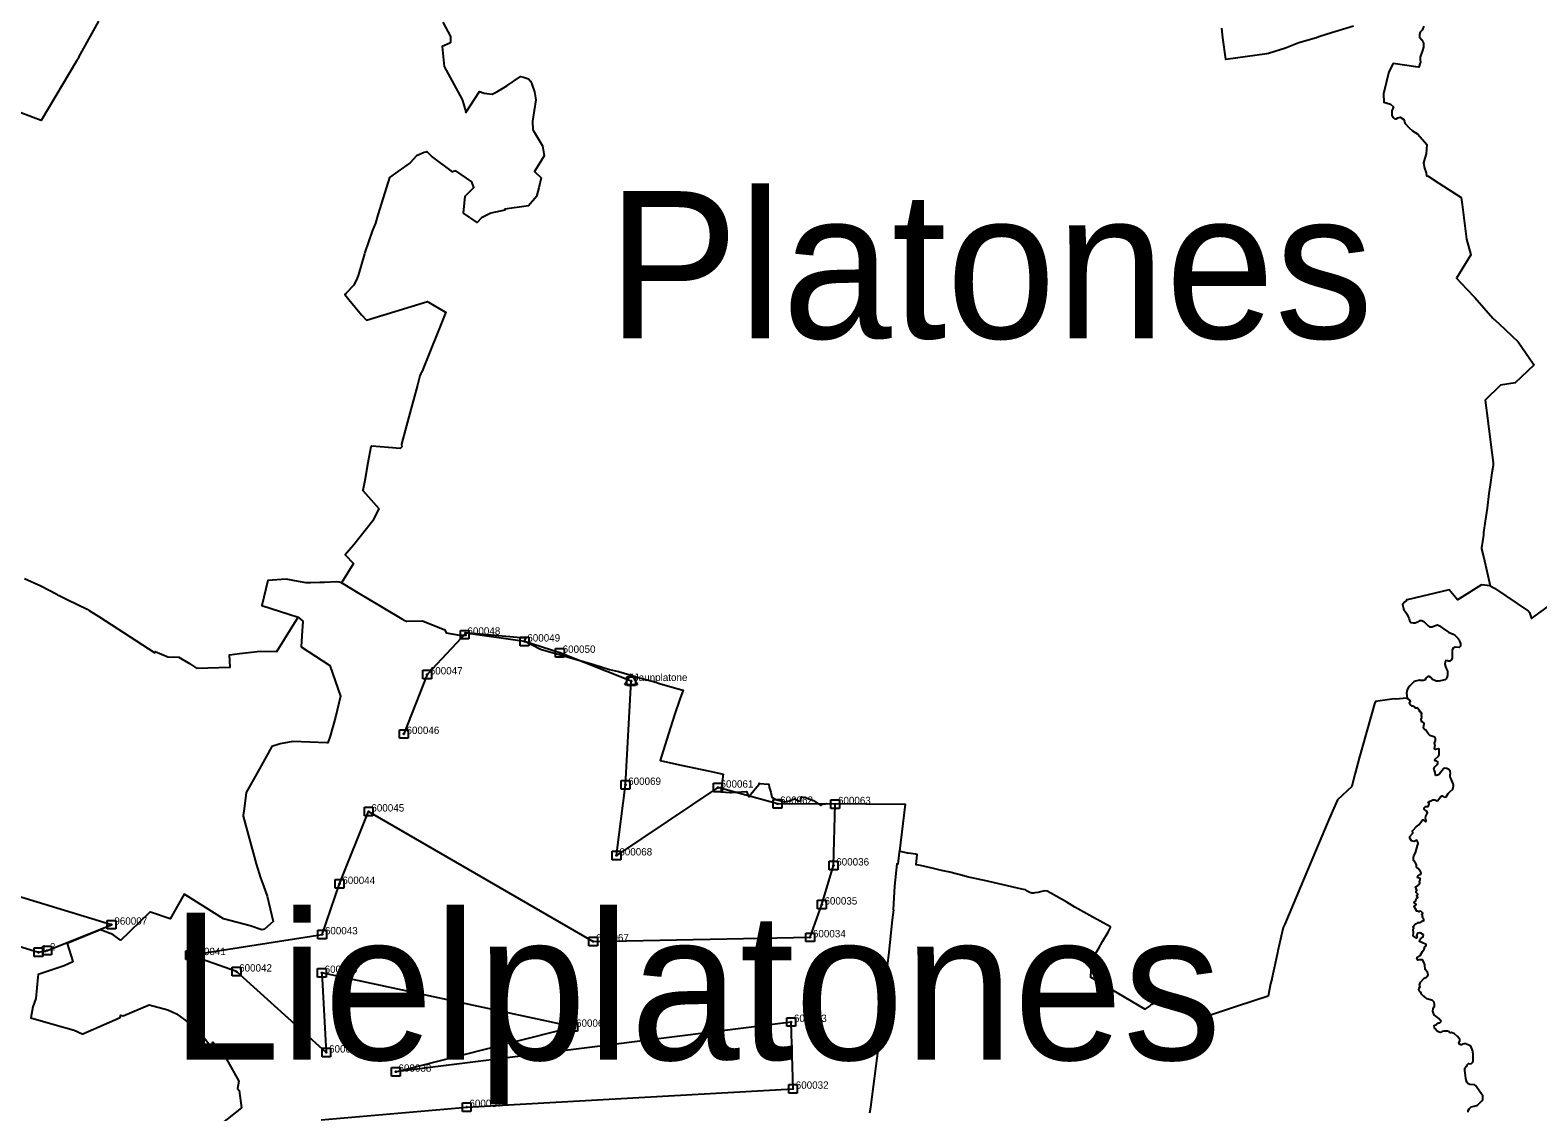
# Model space of a CAD drawing. Extents: x 462479 to 502016, y 241775 to 305873.
# Drawn here: x 474079 to 486368, y 257820 to 266634 of the extents above; entities that cross this region are included whole.
import ezdxf

# ---------------------------------------------------------------- set-up
doc = ezdxf.new("R2010")
doc.units = 0
for name, color, linetype in [('Default', 7, 'Continuous'), ('Level 19', 7, 'Continuous'), ('Level 51', 7, 'Continuous'), ('pagastu_nosaukumi', 7, 'Continuous'), ('pagastu_robezas', 7, 'Continuous')]:
    doc.layers.add(name, color=color, linetype=linetype)

msp = doc.modelspace()

# ---------------------------------------------------------------- linework, layer by layer
at = {"layer": 'Default'}
for points in [[(476451, 257755), (477637, 257859), (480297, 258008), (480282, 258552), (477059, 258147), (478506, 258513), (476457, 258952), (476493, 258303), (475760, 258963), (475384, 259097), (476459, 259266), (476601, 259677), (476838, 260267), (478669, 259209), (480437, 259242), (480531, 259509), (480627, 259827), (480641, 260327), (480170, 260330), (479684, 260462), (478859, 259909), (478931, 260484), (478977, 261330), (478397, 261560), (478109, 261652), (477631, 261720), (477314, 261384), (477124, 260899)], [(473787, 259230), (474148, 259120), (474218, 259135), (474743, 259345), (473431, 259743)]]:
    msp.add_lwpolyline(points, dxfattribs=at)
at = {"layer": 'Level 19'}
for p, q in [((477586, 261743), (477656, 261743)), ((477586, 261673), (477586, 261743)), ((477656, 261673), (477586, 261673)), ((477656, 261743), (477656, 261673)), ((478074, 261687), (478144, 261687)), ((478074, 261617), (478074, 261687)), ((478144, 261687), (478144, 261617)), ((478144, 261617), (478074, 261617)), ((478362, 261595), (478432, 261595)), ((478362, 261525), (478362, 261595)), ((478432, 261525), (478362, 261525)), ((478432, 261595), (478432, 261525)), ((477279, 261419), (477349, 261419)), ((477279, 261349), (477279, 261419)), ((477349, 261419), (477349, 261349)), ((477349, 261349), (477279, 261349)), ((478925, 261299), (478977, 261390)), ((479030, 261299), (478925, 261299)), ((478942, 261365), (479012, 261365)), ((478942, 261295), (478942, 261365)), ((478942, 261365), (479012, 261365)), ((478942, 261295), (478942, 261365)), ((478942, 261365), (479012, 261365)), ((478942, 261295), (478942, 261365)), ((479012, 261295), (478942, 261295)), ((479012, 261295), (478942, 261295)), ((479012, 261295), (478942, 261295)), ((478977, 261390), (479030, 261299)), ((479012, 261365), (479012, 261295)), ((479012, 261365), (479012, 261295)), ((479012, 261365), (479012, 261295)), ((477089, 260934), (477159, 260934)), ((477089, 260864), (477089, 260934)), ((477159, 260934), (477159, 260864)), ((477159, 260864), (477089, 260864)), ((478896, 260519), (478966, 260519)), ((478896, 260449), (478896, 260519)), ((478966, 260449), (478896, 260449)), ((478966, 260519), (478966, 260449)), ((479649, 260497), (479719, 260497)), ((479649, 260427), (479649, 260497)), ((479719, 260427), (479649, 260427)), ((479719, 260497), (479719, 260427)), ((476803, 260302), (476873, 260302)), ((476803, 260232), (476803, 260302)), ((476873, 260302), (476873, 260232)), ((480135, 260365), (480205, 260365)), ((480135, 260295), (480135, 260365)), ((480205, 260295), (480135, 260295)), ((480205, 260365), (480205, 260295)), ((480606, 260362), (480676, 260362)), ((480606, 260292), (480606, 260362)), ((480676, 260292), (480606, 260292)), ((480676, 260362), (480676, 260292)), ((476873, 260232), (476803, 260232)), ((478824, 259944), (478894, 259944)), ((478824, 259874), (478824, 259944)), ((478894, 259944), (478894, 259874)), ((478894, 259874), (478824, 259874)), ((480592, 259862), (480662, 259862)), ((480592, 259792), (480592, 259862)), ((480662, 259862), (480662, 259792)), ((476566, 259712), (476636, 259712)), ((476566, 259642), (476566, 259712)), ((476636, 259712), (476636, 259642)), ((480662, 259792), (480592, 259792)), ((476636, 259642), (476566, 259642)), ((480496, 259544), (480566, 259544)), ((480496, 259474), (480496, 259544)), ((480566, 259474), (480496, 259474)), ((480566, 259544), (480566, 259474)), ((474708, 259380), (474778, 259380)), ((474708, 259310), (474708, 259380)), ((474778, 259310), (474708, 259310)), ((474778, 259380), (474778, 259310)), ((476424, 259301), (476494, 259301)), ((476424, 259231), (476424, 259301)), ((476494, 259231), (476424, 259231)), ((476494, 259301), (476494, 259231)), ((478634, 259244), (478704, 259244)), ((478634, 259174), (478634, 259244)), ((478704, 259244), (478704, 259174)), ((480402, 259277), (480472, 259277)), ((480402, 259207), (480402, 259277)), ((480472, 259207), (480402, 259207)), ((480472, 259277), (480472, 259207)), ((474113, 259155), (474183, 259155)), ((474113, 259085), (474113, 259155)), ((474183, 259085), (474113, 259085)), ((474183, 259170), (474253, 259170)), ((474183, 259100), (474183, 259170)), ((474183, 259155), (474183, 259085)), ((474253, 259100), (474183, 259100)), ((474253, 259170), (474253, 259100)), ((475349, 259132), (475419, 259132)), ((475349, 259062), (475349, 259132)), ((475419, 259062), (475349, 259062)), ((475419, 259132), (475419, 259062)), ((478704, 259174), (478634, 259174)), ((475725, 258998), (475795, 258998)), ((475725, 258928), (475725, 258998)), ((475795, 258998), (475795, 258928)), ((476422, 258987), (476492, 258987)), ((476422, 258917), (476422, 258987)), ((476492, 258987), (476492, 258917)), ((475795, 258928), (475725, 258928)), ((476492, 258917), (476422, 258917)), ((480247, 258587), (480317, 258587)), ((480247, 258517), (480247, 258587)), ((480317, 258587), (480317, 258517)), ((478471, 258548), (478541, 258548)), ((478471, 258478), (478471, 258548)), ((478541, 258478), (478471, 258478)), ((478541, 258548), (478541, 258478)), ((480317, 258517), (480247, 258517)), ((476458, 258338), (476528, 258338)), ((476458, 258268), (476458, 258338)), ((476458, 258338), (476528, 258338)), ((476458, 258268), (476458, 258338)), ((476528, 258338), (476528, 258268)), ((476528, 258338), (476528, 258268)), ((476528, 258268), (476458, 258268)), ((476528, 258268), (476458, 258268)), ((477024, 258182), (477094, 258182)), ((477024, 258112), (477024, 258182)), ((477094, 258112), (477024, 258112)), ((477094, 258182), (477094, 258112)), ((480262, 258043), (480332, 258043)), ((480262, 257973), (480262, 258043)), ((480332, 257973), (480262, 257973)), ((480332, 258043), (480332, 257973)), ((477602, 257894), (477672, 257894)), ((477602, 257824), (477602, 257894)), ((477672, 257894), (477672, 257824)), ((477672, 257824), (477602, 257824))]:
    msp.add_line(p, q, dxfattribs=at)
for centre in [(477621, 261708), (478109, 261652), (478397, 261560), (477314, 261384), (478977, 261330), (478977, 261330), (478977, 261330), (478977, 261330), (477124, 260899), (478931, 260484), (479684, 260462), (480170, 260330), (480641, 260327), (476838, 260267), (478859, 259909), (480627, 259827), (476601, 259677), (480531, 259509), (474743, 259345), (476459, 259265), (478669, 259209), (480437, 259242), (474148, 259119), (474218, 259135), (475384, 259097), (475760, 258962), (476457, 258952), (478506, 258513), (480282, 258552), (476493, 258303), (476493, 258303), (477059, 258147), (480297, 258008), (477637, 257859)]:
    msp.add_circle(centre, 3.5, dxfattribs=at)
at = {"layer": 'pagastu_robezas'}
for points in [[(474637, 266706), (474474, 266413), (474476, 266407), (474459, 266386), (474170, 265897), (474003, 265959)], [(477442, 266700), (477505, 266582), (477505, 266533), (477501, 266529), (477437, 266500), (477451, 266365), (477453, 266338), (477599, 266069), (477601, 266066), (477604, 266061), (477630, 265969), (477631, 265964), (477742, 266135), (477779, 266121), (477845, 266111), (477884, 266131), (477965, 266180), (478077, 266256), (478099, 266250), (478142, 266236), (478158, 266218), (478168, 266197), (478169, 266195), (478191, 266131), (478200, 266067), (478173, 265892), (478177, 265820), (478181, 265814), (478256, 265692), (478270, 265611), (478189, 265483), (478244, 265431), (478224, 265348), (478210, 265290), (478208, 265282), (478141, 265202), (477948, 265174), (477949, 265167), (477834, 265143), (477758, 265104), (477722, 265066), (477610, 265143), (477626, 265282), (477695, 265353), (477679, 265397), (477550, 265487), (477522, 265480), (477350, 265607), (477311, 265644), (477303, 265641), (477291, 265636), (477229, 265611), (477177, 265552), (477076, 265481), (477008, 265432), (476915, 265136), (476912, 265128), (476893, 265061), (476866, 264996), (476808, 264821), (476804, 264811), (476754, 264643), (476744, 264613), (476718, 264557), (476651, 264488), (476649, 264483), (476644, 264481), (476676, 264439), (476781, 264313), (476820, 264270), (477319, 264422), (477320, 264421), (477327, 264417), (477465, 264337), (477468, 264335), (477274, 263854), (477271, 263846), (477263, 263837), (477256, 263818), (477236, 263742), (477166, 263482), (477107, 263261), (477109, 263240), (477096, 263225), (476999, 263232), (477000, 263234), (476864, 263243), (476858, 263241), (476856, 263238), (476831, 263108), (476806, 262964), (476791, 262883), (476922, 262736), (476872, 262636), (476718, 262440), (476646, 262359), (476715, 262288), (476618, 262131)], [(483789, 266649), (483799, 266570), (483822, 266398), (483826, 266398), (484160, 266443), (484172, 266447), (484311, 266491), (484419, 266533), (484563, 266575), (484582, 266581), (484652, 266604), (484865, 266670)], [(485439, 266666), (485424, 266633), (485410, 266617), (485404, 266599), (485403, 266577), (485422, 266555), (485435, 266529), (485435, 266496), (485428, 266469), (485415, 266430), (485409, 266413), (485409, 266393), (485411, 266374), (485409, 266368), (485398, 266331), (485375, 266334), (485188, 266363), (485154, 266295), (485109, 266115), (485112, 266047), (485167, 266030), (485193, 266009), (485177, 265977), (485178, 265942), (485186, 265921), (485202, 265912), (485213, 265912), (485227, 265920), (485246, 265925), (485276, 265907), (485280, 265890), (485283, 265876), (485319, 265838), (485346, 265814), (485391, 265785), (485463, 265703), (485459, 265627), (485446, 265592), (485436, 265553), (485443, 265508), (485459, 265470), (485461, 265448), (485473, 265444), (485560, 265387), (485744, 265270), (485751, 265214), (485759, 265147), (485786, 264930), (485821, 264803), (485704, 264614), (485787, 264527), (485855, 264455), (486002, 264287), (486052, 264240), (486207, 264094), (486332, 263913), (486336, 263903), (486183, 263761), (486065, 263742), (485940, 263619), (485958, 263472), (485966, 263405), (485971, 263367), (485982, 263276), (486004, 263107), (486003, 263087), (485993, 263028), (485979, 262929), (485969, 262858), (485954, 262738), (485939, 262632), (485926, 262541), (485925, 262539), (485924, 262520), (485910, 262416), (485910, 262407), (485927, 262335), (485980, 262105)], [(474032, 262166), (474166, 262105), (474297, 262037), (474301, 262032), (474316, 262026), (474380, 261995), (474545, 261915), (474561, 261906), (474638, 261856), (475094, 261559), (475099, 261570), (475202, 261527), (475292, 261524), (475378, 261472), (475434, 261436), (475709, 261444), (475705, 261545), (475785, 261554), (475860, 261562), (475954, 261573), (476091, 261572), (476264, 261851)], [(476618, 262131), (476599, 262137), (476574, 262138), (476479, 262134), (476441, 262132), (476364, 262130), (476329, 262130), (476267, 262140), (476167, 262160), (476015, 262149), (475968, 261947), (476264, 261851)], [(476618, 262131), (476622, 262128), (476628, 262124), (476767, 262041), (476812, 262014), (477109, 261838), (477134, 261823), (477147, 261818), (477149, 261817), (477276, 261821), (477458, 261747), (477469, 261722), (477578, 261703), (477627, 261704), (477633, 261705), (477624, 261726), (478079, 261686), (478119, 261683), (478107, 261659), (478166, 261629), (478240, 261589), (478674, 261464), (478801, 261425), (478875, 261408), (478995, 261373), (479014, 261367), (479028, 261362), (479178, 261320), (479210, 261311), (479350, 261270), (479401, 261255), (479374, 261183), (479332, 261055), (479267, 260848), (479213, 260684), (479371, 260648), (479619, 260597), (479729, 260572), (479709, 260428), (479786, 260422), (479794, 260421), (479837, 260424), (479919, 260429), (479937, 260388), (479942, 260394), (479989, 260452), (480020, 260491), (480023, 260497), (480027, 260496), (480095, 260490), (480101, 260490), (480103, 260465), (480115, 260425), (480125, 260385), (480155, 260368), (480164, 260363), (480230, 260347), (480268, 260353), (480309, 260370), (480347, 260351), (480362, 260357), (480361, 260370), (480367, 260386), (480395, 260380), (480413, 260376), (480464, 260357), (480525, 260317), (480534, 260325), (480536, 260331), (480562, 260330), (480571, 260333), (481211, 260328), (481164, 259943)], [(485980, 262105), (485909, 262114), (485726, 262001), (485713, 261992), (485646, 262074), (485302, 261993), (485297, 261991), (485294, 261983), (485283, 261975), (485265, 261953), (485272, 261920), (485277, 261909), (485288, 261897), (485301, 261879), (485312, 261853), (485318, 261836), (485321, 261823), (485332, 261807), (485352, 261804), (485368, 261805), (485381, 261809), (485392, 261813), (485409, 261823), (485422, 261824), (485438, 261816), (485457, 261797), (485472, 261784), (485486, 261773), (485508, 261773), (485525, 261781), (485549, 261787), (485566, 261781), (485589, 261764), (485641, 261729), (485677, 261712), (485693, 261700), (485719, 261676), (485726, 261667), (485730, 261656), (485737, 261636), (485737, 261624), (485737, 261615), (485726, 261604), (485694, 261607), (485679, 261599), (485669, 261585), (485669, 261571), (485671, 261551), (485671, 261535), (485671, 261519), (485664, 261504), (485657, 261495), (485651, 261492), (485641, 261492), (485632, 261495), (485617, 261498), (485612, 261487), (485609, 261468), (485615, 261448), (485624, 261426), (485632, 261411), (485633, 261388), (485632, 261375), (485629, 261371), (485628, 261359), (485623, 261350), (485623, 261350), (485611, 261340), (485589, 261334), (485576, 261332), (485561, 261328), (485540, 261328), (485533, 261331), (485509, 261344), (485495, 261358), (485483, 261367), (485472, 261366), (485459, 261356), (485455, 261350), (485447, 261338), (485436, 261334), (485421, 261334), (485409, 261335), (485404, 261338), (485392, 261336), (485371, 261328), (485357, 261323), (485340, 261308), (485324, 261291), (485311, 261271), (485303, 261258), (485298, 261231), (485299, 261212), (485304, 261192)], [(485980, 262105), (486015, 262087), (486292, 261900), (486299, 261890), (486313, 261848), (486317, 261839), (486475, 261953)], [(476264, 261851), (476302, 261818), (476294, 261699), (476289, 261608), (476522, 261458), (476608, 261206), (476568, 261036), (476525, 260881), (476505, 260828), (476496, 260828), (476219, 260838), (476118, 260818), (476049, 260796), (475949, 260616), (475841, 260421), (475821, 260268), (475816, 260237), (475816, 260228), (475921, 259842), (475957, 259728), (475982, 259662), (476010, 259578), (476060, 259371), (475989, 259309), (475967, 259302), (475871, 259336), (475655, 259394), (475341, 259591), (475335, 259595), (475219, 259392), (475059, 259446), (475053, 259444), (474893, 259292), (474890, 259288), (474885, 259283), (474884, 259282), (474817, 259219), (474816, 259220), (474753, 259265), (474653, 259303), (474565, 259267), (474380, 259193), (474426, 259045), (474428, 259041), (474355, 259009), (474144, 258940), (474142, 258917), (474126, 258744), (474101, 258675), (474085, 258586), (474284, 258529), (474438, 258486), (474504, 258455), (474507, 258456), (474812, 258588), (474817, 258608), (474838, 258603), (475050, 258691), (475202, 258650), (475271, 258618), (475382, 258538), (475381, 258535), (475451, 258482), (475555, 258349), (475569, 258388), (475651, 258298), (475781, 258071), (475769, 258009), (475782, 257993), (475802, 257852), (475465, 257586)], [(485304, 261192), (485209, 261182), (485198, 261186), (485046, 261163), (485038, 261144), (484913, 260703), (484878, 260579), (484876, 260571), (484852, 260472), (484734, 260361), (484695, 260270), (484652, 260170), (484513, 259840), (484320, 259382), (484314, 259368), (484305, 259350), (484292, 259321), (484255, 259155), (484249, 259133), (484245, 259116), (484200, 258905), (484200, 258902), (484190, 258864), (484171, 258762), (483921, 258680), (483912, 258677), (483609, 258578), (483590, 258572), (483586, 258601), (483531, 258633), (483513, 258649), (483494, 258678), (483469, 258683), (483453, 258663), (483431, 258687), (483400, 258723), (483372, 258775), (483337, 258737), (483334, 258740), (483298, 258725), (483214, 258691), (483210, 258688), (483206, 258685), (483164, 258657), (482728, 258914), (482724, 258915), (482727, 258971), (482730, 259048), (482731, 259053), (482753, 259090), (482790, 259154), (482821, 259209), (482865, 259284), (482882, 259316), (482885, 259322), (482886, 259327), (482802, 259374), (482717, 259421), (482594, 259489), (482528, 259528), (482399, 259601), (482368, 259617), (482348, 259620), (482293, 259606), (482268, 259604), (482258, 259602), (482245, 259603), (482227, 259608), (482199, 259620), (482191, 259628), (482163, 259635), (481857, 259705), (481831, 259711), (481716, 259736), (481689, 259744), (481574, 259772), (481508, 259786), (481442, 259802), (481337, 259826), (481320, 259830), (481302, 259832), (481308, 259918), (481299, 259920), (481298, 259920), (481235, 259927), (481230, 259927), (481172, 259941), (481164, 259943)], [(485800, 257816), (485799, 257830), (485809, 257844), (485824, 257860), (485850, 257865), (485875, 257874), (485913, 257911), (485919, 257921), (485919, 257950), (485861, 258034), (485853, 258041), (485814, 258042), (485800, 258047), (485789, 258063), (485780, 258091), (485779, 258114), (485774, 258160), (485773, 258177), (485781, 258187), (485791, 258195), (485791, 258202), (485804, 258213), (485814, 258211), (485827, 258213), (485834, 258219), (485839, 258226), (485841, 258239), (485841, 258250), (485841, 258256), (485841, 258285), (485839, 258314), (485823, 258354), (485806, 258364), (485793, 258369), (485780, 258374), (485764, 258374), (485753, 258372), (485745, 258365), (485738, 258365), (485732, 258369), (485723, 258381), (485727, 258391), (485732, 258397), (485733, 258410), (485725, 258421), (485713, 258434), (485689, 258455), (485665, 258467), (485657, 258465), (485646, 258472), (485633, 258476), (485614, 258477), (485602, 258478), (485587, 258475), (485582, 258468), (485573, 258466), (485563, 258468), (485548, 258478), (485530, 258495), (485527, 258501), (485523, 258523), (485543, 258533), (485558, 258544), (485570, 258546), (485576, 258551), (485579, 258557), (485576, 258565), (485562, 258580), (485537, 258600), (485527, 258605), (485518, 258624), (485512, 258641), (485515, 258658), (485520, 258673), (485526, 258682), (485527, 258695), (485524, 258713), (485510, 258726), (485493, 258733), (485464, 258740), (485454, 258750), (485443, 258756), (485440, 258760), (485420, 258780), (485414, 258795), (485405, 258801), (485404, 258802), (485402, 258807), (485400, 258811), (485399, 258816), (485401, 258828), (485408, 258842), (485404, 258853), (485408, 258868), (485412, 258874), (485415, 258878), (485442, 258909), (485461, 258918), (485468, 258924), (485473, 258935), (485469, 258958), (485449, 258981), (485448, 259017), (485439, 259040), (485427, 259059), (485403, 259058), (485389, 259055), (485382, 259075), (485409, 259095), (485428, 259126), (485442, 259145), (485448, 259164), (485458, 259172), (485458, 259183), (485423, 259199), (485404, 259209), (485405, 259222), (485411, 259231), (485433, 259245), (485435, 259263), (485415, 259276), (485405, 259279), (485386, 259275), (485378, 259258), (485384, 259245), (485379, 259236), (485352, 259254), (485356, 259280), (485352, 259307), (485357, 259316), (485352, 259331), (485370, 259353), (485381, 259355), (485391, 259364), (485406, 259364), (485424, 259375), (485426, 259377), (485433, 259378), (485439, 259377), (485439, 259379), (485439, 259381), (485438, 259387), (485436, 259392), (485435, 259395), (485433, 259398), (485429, 259403), (485428, 259408), (485430, 259416), (485428, 259421), (485421, 259429), (485428, 259432), (485431, 259440), (485417, 259452), (485406, 259455), (485399, 259451), (485392, 259456), (485379, 259455), (485378, 259460), (485363, 259487), (485360, 259497), (485376, 259507), (485376, 259511), (485359, 259522), (485362, 259530), (485373, 259538), (485380, 259560), (485391, 259566), (485380, 259579), (485388, 259586), (485391, 259594), (485383, 259603), (485377, 259606), (485376, 259612), (485382, 259626), (485370, 259653), (485391, 259665), (485403, 259674), (485405, 259683), (485404, 259697), (485410, 259707), (485408, 259720), (485391, 259727), (485386, 259732), (485392, 259743), (485406, 259753), (485415, 259756), (485416, 259767), (485412, 259778), (485393, 259803), (485381, 259812), (485380, 259816), (485380, 259831), (485376, 259838), (485371, 259848), (485356, 259868), (485355, 259892), (485357, 259907), (485371, 259930), (485387, 259990), (485393, 260005), (485389, 260018), (485382, 260033), (485360, 260024), (485338, 260029), (485325, 260049), (485325, 260063), (485348, 260090), (485346, 260109), (485352, 260115), (485377, 260143), (485399, 260158), (485417, 260184), (485427, 260200), (485434, 260198), (485450, 260187), (485457, 260189), (485454, 260201), (485452, 260212), (485456, 260230), (485468, 260257), (485460, 260270), (485441, 260285), (485442, 260297), (485453, 260309), (485473, 260308), (485483, 260326), (485475, 260337), (485476, 260344), (485490, 260351), (485511, 260361), (485529, 260363), (485547, 260353), (485552, 260357), (485574, 260388), (485588, 260395), (485604, 260384), (485621, 260388), (485636, 260414), (485652, 260428), (485674, 260448), (485679, 260463), (485682, 260474), (485681, 260481), (485678, 260492), (485659, 260539), (485653, 260551), (485653, 260565), (485657, 260580), (485653, 260595), (485643, 260609), (485627, 260617), (485625, 260617), (485610, 260619), (485599, 260614), (485566, 260574), (485557, 260566), (485549, 260562), (485538, 260561), (485533, 260565), (485531, 260584), (485527, 260601), (485521, 260612), (485522, 260620), (485528, 260632), (485540, 260642), (485552, 260657), (485552, 260671), (485544, 260678), (485530, 260680), (485528, 260687), (485532, 260695), (485558, 260717), (485565, 260729), (485565, 260765), (485564, 260774), (485556, 260778), (485535, 260772), (485529, 260776), (485527, 260784), (485531, 260806), (485526, 260823), (485534, 260847), (485534, 260863), (485528, 260872), (485489, 260886), (485479, 260895), (485472, 260905), (485467, 260913), (485455, 260931), (485450, 260934), (485443, 260936), (485435, 260947), (485439, 260969), (485441, 260979), (485442, 260983), (485441, 260988), (485432, 260995), (485429, 260999), (485423, 260997), (485421, 261003), (485419, 261009), (485417, 261014), (485418, 261024), (485422, 261033), (485423, 261041), (485420, 261050), (485419, 261056), (485422, 261061), (485422, 261065), (485418, 261067), (485420, 261071), (485419, 261073), (485415, 261075), (485411, 261078), (485406, 261080), (485403, 261082), (485404, 261088), (485406, 261090), (485404, 261092), (485400, 261093), (485398, 261095), (485396, 261103), (485392, 261107), (485388, 261111), (485378, 261110), (485372, 261110), (485368, 261111), (485365, 261117), (485354, 261122), (485348, 261126), (485341, 261126), (485336, 261132), (485334, 261135), (485329, 261135), (485328, 261136), (485329, 261139), (485327, 261142), (485326, 261146), (485323, 261150), (485323, 261154), (485325, 261159), (485326, 261161), (485329, 261163), (485328, 261168), (485327, 261172), (485322, 261177), (485319, 261177), (485317, 261176), (485317, 261181), (485310, 261184), (485306, 261185), (485304, 261192)], [(481164, 259943), (481163, 259936), (481151, 259839), (481144, 259840), (481124, 259658), (481113, 259468), (481115, 259466), (481104, 259385), (481078, 259122), (481023, 258666), (481008, 258540), (480991, 258341), (480929, 257859), (480928, 257855), (480921, 257808)]]:
    msp.add_lwpolyline(points, dxfattribs=at)

# ---------------------------------------------------------------- texts
at = {"layer": 'Level 51'}
for s, p in [(' 600048', (477621, 261708)), (' 600049', (478109, 261652)), (' 600050', (478397, 261560)), (' 600047', (477314, 261384)), (' Jaunplatone', (478977, 261330)), (' Jaunplatone', (478977, 261330)), (' Jaunplatone', (478977, 261330)), (' Jaunplatone', (478977, 261330)), (' 600046', (477124, 260899)), (' 600069', (478931, 260484)), (' 600061', (479684, 260462)), (' 600045', (476838, 260267)), (' 600062', (480170, 260330)), (' 600063', (480641, 260327)), (' 600068', (478859, 259909)), (' 600036', (480627, 259827)), (' 600044', (476601, 259677)), (' 600035', (480531, 259509)), (' 960007', (474743, 259345)), (' 600043', (476459, 259266)), (' 2', (474218, 259135)), (' 600067', (478669, 259209)), (' 600034', (480437, 259242)), (' 1', (474148, 259120)), (' 600041', (475384, 259097)), (' 600042', (475760, 258963)), (' 600040', (476457, 258952)), (' 600066', (478506, 258513)), (' 600033', (480282, 258552)), (' 600039', (476493, 258303)), (' 600039', (476493, 258303)), (' 600038', (477059, 258147)), (' 600032', (480297, 258008)), (' 600037', (477637, 257859))]:
    msp.add_text(s, height=60, dxfattribs=at).set_placement(p)
at = {"layer": 'pagastu_nosaukumi'}
for s, p in [('Platones', (478782, 264122)), ('Lielplatones', (475224, 258244))]:
    msp.add_text(s, height=1200, dxfattribs=at).set_placement(p)

doc.saveas('drawing.dxf')
